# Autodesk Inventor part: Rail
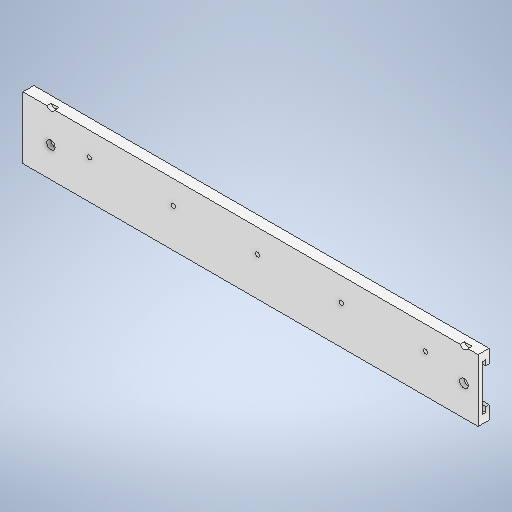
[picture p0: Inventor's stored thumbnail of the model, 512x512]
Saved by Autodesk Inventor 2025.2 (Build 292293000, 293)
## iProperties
Created: 2025-09
Part Number: Rail
Material: Generic
Document SubType Name: Modeling
Designer: tyler
Density: 1 g/cm^3
Appearance: Default
Author: tyler
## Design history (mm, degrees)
sketch "Sketch1"
  geometry: L1 (-6.35, 1.588)-(6.35, 1.588); L2 (6.35, 1.588)-(6.35, -1.587); L3 (6.35, -1.587)-(-6.35, -1.588); L4 (-6.35, -1.588)-(-6.35, 1.588); L5 (-6.35, 1.588)-(6.35, -1.587); L6 (6.35, 1.588)-(-6.35, -1.588); L7 (6.35, -1.587)-(6.35, -4.127); L8 (6.35, -4.127)-(6.35, -6.667); L9 (6.35, -6.667)-(-3.81, -6.668); L10 (-3.81, -6.668)-(-3.81, -4.128); L11 (-3.81, -4.128)-(0, -4.128); L12 (0, -4.128)-(0, -1.588); L13 (-6.35, -1.588)-(-19.05, -1.588); L14 (-19.05, -1.588)-(-19.05, 1.588); L15 (-19.05, 1.588)-(-6.35, 1.588); L16 (-3.81, -6.668)-(-30.48, -6.668); L17 (-30.48, -6.668)-(-30.48, -4.128); L18 (-30.48, -4.128)-(-34.29, -4.128); L19 (-34.29, -4.128)-(-34.29, -1.588); L20 (-34.29, -1.588)-(-19.05, -1.588); L21 (-30.48, -6.668)-(-40.64, -6.668); L22 (-40.64, -6.668)-(-40.64, 1.587); L23 (-40.64, 1.587)-(-19.05, 1.588); 1 further point
  constraints: 46 end point, 9 perpendicular, 5 horizontal, 3 equal length, 3 midpoint, 2 vertical, 1 point on line
  dimensions: "d0" = 12.7 distance of L2.end L3.end; "d1" = 3.175 distance of L1.end L2.end; "d2" = 2.54 distance of L2.end L7.end; "d3" = 2.54 distance of L7.end L8.end; "d4" = 10.16 distance of L8.end L9.end; "d5" = 3.81 distance of L10.end L11.end; "d6" = 12.7 distance of L3.end L13.end; "d24" = 26.67 distance of L9.end L16.end; "d25" = 3.81 distance of L17.end L18.end; "d26" = 10.16 distance of L16.end L21.end
extrude "Extrusion1" new body sketch "Sketch1" distance "d7" = 343.916; taper "d8" = 0 deg
sketch "Sketch6"
  geometry: L1 (-343.916, 30.48)-(-343.916, 22.86); L2 (-343.916, 40.64)-(-343.916, -6.35) reference; L3 (-343.916, 22.86)-(0, 22.86); L4 (-177.151, 22.86)-(-240.651, 22.86); L5 (-240.651, 22.86)-(-304.151, 22.86); L6 (-177.151, 22.86)-(-113.651, 22.86); L7 (-113.651, 22.86)-(-50.151, 22.86); C1 r 1.587 at (-177.151, 22.86); C2 r 1.588 at (-304.151, 22.86); C3 r 1.587 at (-240.651, 22.86); C4 r 1.588 at (-113.651, 22.86); C5 r 1.543 at (-50.151, 22.86); 1 further point
  constraints: 12 end point, 6 point on line, 5 centre point, 4 coincident, 1 perpendicular
  dimensions: "d27" = 7.62 distance of L1.start L1.end; "d28" = 3.175 diameter of C1; "d29" = 63.5 distance of L4.start L4.end; "d30" = 63.5 distance of L4.end L5.end; "d31" = 63.5 distance of L4.start L6.end; "d32" = 63.5 distance of L6.end L7.end; "d33" = 3.175 diameter of C2; "d34" = 3.175 diameter of C3; "d35" = 3.175 diameter of C4; "d36" = 3.0861 diameter of C5
extrude "Extrusion5" cut sketch "Sketch6" distance "d37" = 63.5 (= d32); taper "d38" = 0 deg
sketch "Sketch7"
  geometry: L1 (50.151, 29.21)-(21.068, 29.21); L2 (21.068, 29.21)-(21.068, 22.86); L3 (21.068, 29.21)-(21.068, 48.26); L4 (21.068, 29.21)-(40.118, 29.21); L5 (304.151, 29.21)-(333.234, 29.21); L6 (333.234, 29.21)-(333.234, 22.86); L7 (0, 10.16)-(343.916, 10.16) reference; L8 (333.234, 29.21)-(333.234, 48.26); L9 (333.234, 29.21)-(352.284, 29.21); C1 r 1.543 at (50.151, 29.21) reference; C2 r 1.588 at (304.151, 29.21) reference; C3 r 3.175 at (21.068, 22.86); C4 r 3.175 at (21.068, 48.26); C5 r 3.175 at (333.234, 22.86); C6 r 3.175 at (333.234, 48.26); 1 further point
  constraints: 16 end point, 4 centre point, 4 coincident, 4 horizontal, 3 perpendicular, 3 vertical
  dimensions: "d39" = 29.083 distance of L1.start L1.end; "d40" = 6.35 distance of L1.end L2.end; "d41" = 19.05 distance of L1.end L3.end; "d42" = 90 deg angle of L4 L3 (derived); "d43" = 29.083 distance of L5.start L5.end; "d44" = 19.05 distance of L5.end L8.end; "d45" = 90 deg angle of L9 L8 (derived); "d46" = 6.35 diameter of C3; "d47" = 6.35 diameter of C4; "d48" = 6.35 diameter of C5; "d49" = 6.35 diameter of C6
extrude "Extrusion6" cut sketch "Sketch7" distance "d50" = 3.175; taper "d51" = 0 deg
body "Solid1"
